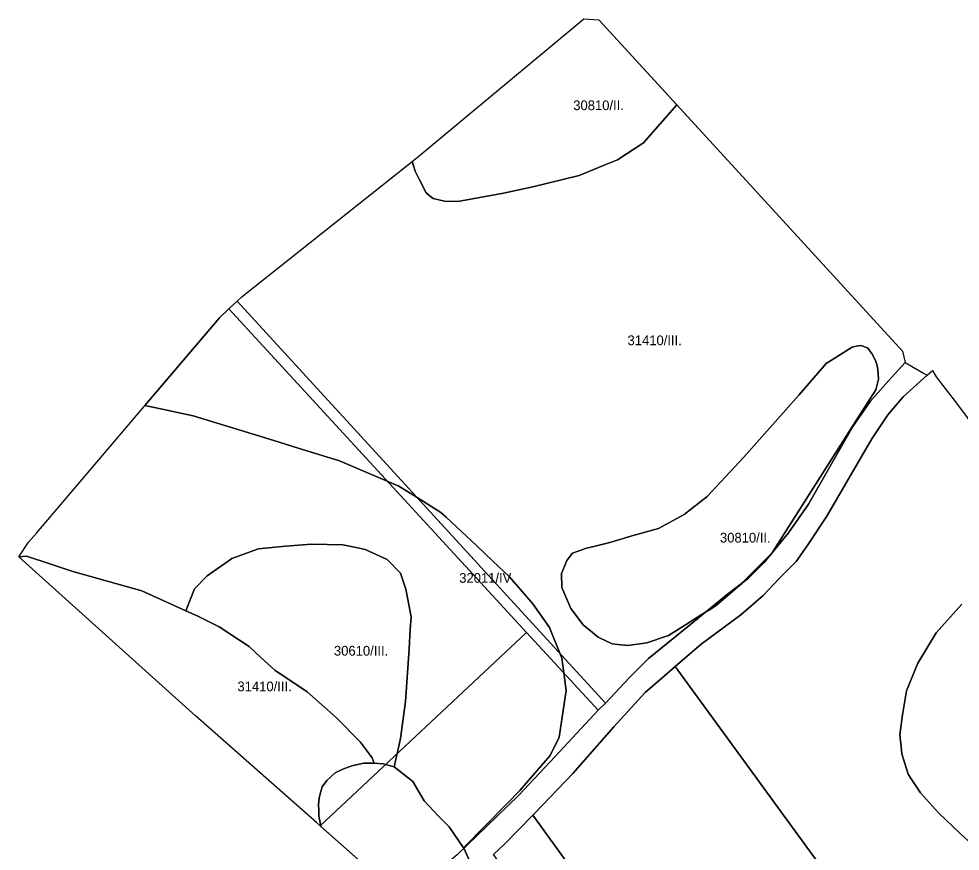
# Model space of a CAD drawing. Extents: x -522079 to -518833, y -1142400 to -1139961.
# Drawn here: x -522079.2 to -521596.1, y -1140463.4 to -1140035.9 of the extents above; entities that cross this region are included whole.
import ezdxf

# ---------------------------------------------------------------- set-up
doc = ezdxf.new("R2010")
doc.units = 0
for name, color, linetype in [('95560013', 7, 'Continuous'), ('95640013', 7, 'Continuous'), ('95660013', 7, 'Continuous')]:
    doc.layers.add(name, color=color, linetype=linetype)

msp = doc.modelspace()

# ---------------------------------------------------------------- linework, layer by layer
at = {"layer": '95560013'}
for points in [[(-521755.99, -1140364.38), (-521765.79, -1140374.26), (-521778.1, -1140387.34), (-521967.11, -1140180.95), (-521964.54, -1140178.59), (-521874.73, -1140107.13), (-521789.25, -1140035.92), (-521781.62, -1140036.36), (-521703.78, -1140121.15), (-521625.65, -1140206.61), (-521624.31, -1140212.38), (-521632.85, -1140221.77), (-521642.31, -1140232.52), (-521651.12, -1140245.38), (-521673.96, -1140285.19), (-521684.15, -1140299.89), (-521696.71, -1140315.1), (-521704.79, -1140323.18), (-521715.5, -1140331.4), (-521736.25, -1140348.4)], [(-521971.46, -1140184.95), (-521967.11, -1140180.95), (-521778.1, -1140387.34), (-521781.95, -1140390.97), (-521818.63, -1140351.09)], [(-521926.43, -1140448.75), (-521988.52, -1140393.86), (-522079.24, -1140312.2), (-522074.19, -1140304.73), (-522070.23, -1140300.06), (-521976.31, -1140189.41), (-521971.46, -1140184.95), (-521818.63, -1140351.09), (-521924.65, -1140450.32)], [(-521924.65, -1140450.32), (-521818.63, -1140351.09), (-521781.95, -1140390.97), (-521803.88, -1140414.74), (-521822.79, -1140434.86), (-521839, -1140450.48), (-521854.3, -1140465.27), (-521876.66, -1140484.09), (-521882.18, -1140488.56), (-521891.73, -1140479.43)], [(-521747.91, -1140373.33), (-521742.3, -1140368.5), (-521638.02, -1140511.86), (-521697.45, -1140535.57), (-521738.18, -1140551.68), (-521815.4, -1140444.86), (-521814.39, -1140443.83), (-521794.87, -1140423.48), (-521773.82, -1140399.6), (-521757.78, -1140381.98)], [(-521829.77, -1140459.58), (-521815.4, -1140444.86), (-521738.18, -1140551.68), (-521764.87, -1140562.24), (-521835.62, -1140465.09)]]:
    msp.add_lwpolyline(points, close=True, dxfattribs=at)
msp.add_lwpolyline([(-521592.51, -1140508.64), (-521606.9, -1140511.13), (-521606.6, -1140521.1), (-521611.18, -1140517.57), (-521625.07, -1140510.37), (-521636.41, -1140511.21), (-521638.02, -1140511.86), (-521742.3, -1140368.5), (-521728.93, -1140357.06), (-521708.67, -1140341.98), (-521697.12, -1140332.11), (-521688.85, -1140323.27), (-521680.22, -1140314.66), (-521674.58, -1140306.67), (-521664.44, -1140291.34), (-521641.46, -1140251.62), (-521633.25, -1140239.25), (-521625.36, -1140230.13), (-521613.09, -1140218.9), (-521610.22, -1140216.5), (-521608.33, -1140219.87), (-521596.95, -1140234.61), (-521579.62, -1140257.92)], dxfattribs=at)
at = {"layer": '95640013'}
msp.add_lwpolyline([(-521854.3, -1140465.27), (-521839, -1140450.48), (-521822.79, -1140434.86), (-521803.88, -1140414.74), (-521781.95, -1140390.97), (-521778.1, -1140387.34), (-521765.79, -1140374.26), (-521755.99, -1140364.38), (-521736.25, -1140348.4), (-521715.5, -1140331.4), (-521704.79, -1140323.18), (-521696.71, -1140315.1), (-521684.15, -1140299.89), (-521673.96, -1140285.19), (-521651.12, -1140245.38), (-521642.31, -1140232.52), (-521632.85, -1140221.77), (-521624.31, -1140212.38), (-521620.19, -1140214.77), (-521614.87, -1140217.86), (-521613.09, -1140218.9), (-521625.36, -1140230.13), (-521633.25, -1140239.25), (-521641.46, -1140251.62), (-521664.44, -1140291.34), (-521674.58, -1140306.67), (-521680.22, -1140314.66), (-521688.85, -1140323.27), (-521697.12, -1140332.11), (-521708.67, -1140341.98), (-521728.93, -1140357.06), (-521742.3, -1140368.5), (-521747.91, -1140373.33), (-521757.78, -1140381.98), (-521773.82, -1140399.6), (-521794.87, -1140423.48), (-521814.39, -1140443.83), (-521815.4, -1140444.86), (-521829.77, -1140459.58), (-521835.62, -1140465.09)], dxfattribs=at)
at = {"layer": '95660013'}
for points in [[(-521781.62, -1140036.36), (-521741.42, -1140080.14), (-521758.57, -1140099.56), (-521772.02, -1140108.33), (-521778.76, -1140111.12), (-521791.65, -1140116.47), (-521815.34, -1140122.25), (-521830.49, -1140125.46), (-521853.96, -1140129.74), (-521860.79, -1140129.52), (-521866.55, -1140128.24), (-521867.94, -1140127.1), (-521870.18, -1140125.25), (-521873.59, -1140118.61), (-521875.75, -1140114.18), (-521877.32, -1140109.19), (-521874.73, -1140107.13), (-521789.25, -1140035.92)], [(-522070.23, -1140300.06), (-521976.31, -1140189.41), (-522014.56, -1140234.48), (-522010.4, -1140235.32), (-521989.67, -1140239.88), (-521958.99, -1140249.25), (-521948.36, -1140252.5), (-521935.79, -1140256.37), (-521914.67, -1140262.86), (-521890.13, -1140273.36), (-521884.13, -1140275.92), (-521874.73, -1140281.82), (-521862.58, -1140289.44), (-521859.94, -1140291.89), (-521844.16, -1140306.56), (-521835.9, -1140314.4), (-521827.55, -1140322.33), (-521821.85, -1140328.89), (-521815.42, -1140336.29), (-521806.89, -1140348.46), (-521801.63, -1140361.65), (-521800.6, -1140364.23), (-521799.58, -1140371.8), (-521798.35, -1140380.9), (-521801.95, -1140404.77), (-521806.44, -1140414.24), (-521822.16, -1140432.26), (-521828.66, -1140438.92), (-521850.92, -1140461.73), (-521858.38, -1140450.93), (-521863.76, -1140445.35), (-521871.21, -1140437.63), (-521877.01, -1140427.67), (-521886.61, -1140420.14), (-521885.07, -1140413.27), (-521883.33, -1140405.55), (-521880.75, -1140386.5), (-521878.87, -1140359.44), (-521878.31, -1140349.52), (-521877.94, -1140342.97), (-521880.52, -1140328.85), (-521883.33, -1140320.62), (-521890.13, -1140313.57), (-521901.39, -1140308.39), (-521906.04, -1140307.43), (-521912.88, -1140306.03), (-521929.06, -1140305.8), (-521942.43, -1140306.74), (-521956.27, -1140308.15), (-521969.87, -1140313.09), (-521971.83, -1140314.47), (-521982.54, -1140322.03), (-521989.1, -1140328.62), (-521993.56, -1140339.91), (-522016.02, -1140329.67), (-522051.48, -1140319.82), (-522063.39, -1140315.84), (-522075.3, -1140311.87), (-522079.24, -1140312.2), (-522074.19, -1140304.73)], [(-521756.91, -1140356.37), (-521766.66, -1140357.81), (-521771.83, -1140357.25), (-521774.68, -1140356.94), (-521777.62, -1140355.53), (-521781.85, -1140353.5), (-521789.59, -1140347.17), (-521795.89, -1140338.83), (-521800.48, -1140327.91), (-521800.76, -1140320.72), (-521799.03, -1140316.71), (-521797.9, -1140314.1), (-521795.03, -1140310.36), (-521787.87, -1140307.78), (-521784.1, -1140306.88), (-521775.83, -1140304.91), (-521763.4, -1140301.11), (-521762.65, -1140300.88), (-521750.89, -1140297.72), (-521737.71, -1140290.53), (-521725.96, -1140281.33), (-521707.33, -1140261.2), (-521678.96, -1140229.29), (-521664.91, -1140212.9), (-521651.44, -1140204.56), (-521649.44, -1140203.99), (-521647.14, -1140203.7), (-521643.7, -1140204.85), (-521641.41, -1140207.73), (-521639.4, -1140211.75), (-521638.75, -1140214.2), (-521638.26, -1140216.07), (-521637.97, -1140220.95), (-521639.4, -1140226.41), (-521649.44, -1140242.23), (-521671.5, -1140277.01), (-521691.97, -1140309.36), (-521692.43, -1140310.08), (-521693.23, -1140310.89), (-521707.75, -1140325.45), (-521708.19, -1140325.89), (-521721.09, -1140337.1), (-521723.86, -1140338.86), (-521727.1, -1140340.91), (-521736.56, -1140346.88), (-521737.49, -1140347.46), (-521745.74, -1140352.63)], [(-521771.83, -1140357.25), (-521766.66, -1140357.81), (-521756.91, -1140356.37), (-521745.74, -1140352.63), (-521737.49, -1140347.46), (-521736.56, -1140346.88), (-521727.1, -1140340.91), (-521723.86, -1140338.86), (-521721.09, -1140337.1), (-521708.19, -1140325.89), (-521707.75, -1140325.45), (-521693.23, -1140310.89), (-521692.43, -1140310.08), (-521691.97, -1140309.36), (-521671.5, -1140277.01), (-521649.44, -1140242.23), (-521639.4, -1140226.41), (-521637.97, -1140220.95), (-521638.26, -1140216.07), (-521638.75, -1140214.2), (-521639.4, -1140211.75), (-521641.41, -1140207.73), (-521643.7, -1140204.85), (-521647.14, -1140203.7), (-521649.44, -1140203.99), (-521651.44, -1140204.56), (-521664.91, -1140212.9), (-521678.96, -1140229.29), (-521707.33, -1140261.2), (-521725.96, -1140281.33), (-521737.71, -1140290.53), (-521750.89, -1140297.72), (-521762.65, -1140300.88), (-521763.4, -1140301.11), (-521775.83, -1140304.91), (-521784.1, -1140306.88), (-521787.87, -1140307.78), (-521795.03, -1140310.36), (-521797.9, -1140314.1), (-521799.03, -1140316.71), (-521800.76, -1140320.72), (-521800.48, -1140327.91), (-521795.89, -1140338.83), (-521789.59, -1140347.17), (-521781.85, -1140353.5), (-521777.62, -1140355.53), (-521774.68, -1140356.94)], [(-521885.07, -1140413.27), (-521886.61, -1140420.14), (-521891.03, -1140418.85), (-521892.24, -1140418.49), (-521896.93, -1140418.26), (-521897.87, -1140415.43), (-521903.97, -1140407.2), (-521916.4, -1140394.73), (-521931.17, -1140381.56), (-521947.83, -1140370.5), (-521954.94, -1140363.87), (-521960.96, -1140358.26), (-521976.44, -1140348.15), (-521987.7, -1140342.5), (-521993.56, -1140339.91), (-521989.1, -1140328.62), (-521982.54, -1140322.03), (-521971.83, -1140314.47), (-521969.87, -1140313.09), (-521956.27, -1140308.15), (-521942.43, -1140306.74), (-521929.06, -1140305.8), (-521912.88, -1140306.03), (-521906.04, -1140307.43), (-521901.39, -1140308.39), (-521890.13, -1140313.57), (-521883.33, -1140320.62), (-521880.52, -1140328.85), (-521877.94, -1140342.97), (-521878.31, -1140349.52), (-521878.87, -1140359.44), (-521880.75, -1140386.5), (-521883.33, -1140405.55)], [(-522079.24, -1140312.2), (-522075.3, -1140311.87), (-522063.39, -1140315.84), (-522051.48, -1140319.82), (-522016.02, -1140329.67), (-521993.56, -1140339.91), (-521987.7, -1140342.5), (-521976.44, -1140348.15), (-521960.96, -1140358.26), (-521954.94, -1140363.87), (-521947.83, -1140370.5), (-521931.17, -1140381.56), (-521916.4, -1140394.73), (-521903.97, -1140407.2), (-521897.87, -1140415.43), (-521896.93, -1140418.26), (-521902.1, -1140418.23), (-521906.13, -1140419.06), (-521908.3, -1140419.5), (-521910.2, -1140420.25), (-521912.98, -1140421.34), (-521916.8, -1140423.09), (-521921.16, -1140427.15), (-521923.47, -1140430.34), (-521924.82, -1140434.72), (-521925.01, -1140436.18), (-521925.45, -1140439.5), (-521925.33, -1140442.55), (-521925.22, -1140445.48), (-521924.74, -1140447.9), (-521924.38, -1140449.7), (-521924.23, -1140450.69), (-521924.65, -1140450.32), (-521926.43, -1140448.75), (-521988.52, -1140393.86)]]:
    msp.add_lwpolyline(points, close=True, dxfattribs=at)
for points in [[(-521845.96, -1140472.52), (-521850.83, -1140461.92), (-521850.92, -1140461.73), (-521828.66, -1140438.92), (-521822.16, -1140432.26), (-521806.44, -1140414.24), (-521801.95, -1140404.77), (-521798.35, -1140380.9), (-521799.58, -1140371.8), (-521800.6, -1140364.23), (-521801.63, -1140361.65), (-521806.89, -1140348.46), (-521815.42, -1140336.29), (-521821.85, -1140328.89), (-521827.55, -1140322.33), (-521835.9, -1140314.4), (-521844.16, -1140306.56), (-521859.94, -1140291.89), (-521862.58, -1140289.44), (-521874.73, -1140281.82), (-521884.13, -1140275.92), (-521890.13, -1140273.36), (-521914.67, -1140262.86), (-521935.79, -1140256.37), (-521948.36, -1140252.5), (-521958.99, -1140249.25), (-521989.67, -1140239.88), (-522010.4, -1140235.32), (-522014.56, -1140234.48), (-521976.31, -1140189.41), (-521971.46, -1140184.95), (-521967.11, -1140180.95), (-521964.54, -1140178.59), (-521877.32, -1140109.19), (-521875.75, -1140114.18), (-521873.59, -1140118.61), (-521870.18, -1140125.25), (-521867.94, -1140127.1), (-521866.55, -1140128.24), (-521860.79, -1140129.52), (-521853.96, -1140129.74), (-521830.49, -1140125.46), (-521815.34, -1140122.25), (-521791.65, -1140116.47), (-521778.76, -1140111.12), (-521772.02, -1140108.33), (-521758.57, -1140099.56), (-521741.42, -1140080.14), (-521703.78, -1140121.15), (-521625.65, -1140206.61), (-521624.31, -1140212.38), (-521620.19, -1140214.77), (-521614.87, -1140217.86), (-521613.09, -1140218.9), (-521610.22, -1140216.5), (-521608.33, -1140219.87), (-521596.95, -1140234.61), (-521579.62, -1140257.92)], [(-521595.28, -1140336.6), (-521608.32, -1140351.33), (-521617.83, -1140366.87), (-521623.54, -1140381.04), (-521625.71, -1140393.32), (-521627.07, -1140403.67), (-521626.42, -1140409.59), (-521625.99, -1140413.49), (-521622.73, -1140423.85), (-521621.19, -1140426.19), (-521616.47, -1140433.39), (-521607.23, -1140443.75), (-521596.09, -1140454.38), (-521590.17, -1140459.55)], [(-521590.17, -1140459.55), (-521596.09, -1140454.38), (-521607.23, -1140443.75), (-521616.47, -1140433.39), (-521621.19, -1140426.19), (-521622.73, -1140423.85), (-521625.99, -1140413.49), (-521626.42, -1140409.59), (-521627.07, -1140403.67), (-521625.71, -1140393.32), (-521623.54, -1140381.04), (-521617.83, -1140366.87), (-521608.32, -1140351.33), (-521595.28, -1140336.6)], [(-521891.73, -1140479.43), (-521924.23, -1140450.69), (-521924.38, -1140449.7), (-521924.74, -1140447.9), (-521925.22, -1140445.48), (-521925.33, -1140442.55), (-521925.45, -1140439.5), (-521925.01, -1140436.18), (-521924.82, -1140434.72), (-521923.47, -1140430.34), (-521921.16, -1140427.15), (-521916.8, -1140423.09), (-521912.98, -1140421.34), (-521910.2, -1140420.25), (-521908.3, -1140419.5), (-521906.13, -1140419.06), (-521902.1, -1140418.23), (-521896.93, -1140418.26), (-521892.24, -1140418.49), (-521891.03, -1140418.85), (-521886.61, -1140420.14), (-521877.01, -1140427.67), (-521871.21, -1140437.63), (-521863.76, -1140445.35), (-521858.38, -1140450.93), (-521850.92, -1140461.73), (-521850.83, -1140461.92), (-521845.96, -1140472.52)]]:
    msp.add_lwpolyline(points, dxfattribs=at)

# ---------------------------------------------------------------- texts
for s, rotation, p in [('30810/II.', 360, (-521794.68, -1140082.83)), ('31410/III.', 0, (-521766.82, -1140203.55)), ('30810/II.', 0, (-521719.37, -1140304.9)), ('32011/IV.', 360, (-521853.19, -1140325.57)), ('30610/III.', 0, (-521917.51, -1140362.97)), ('31410/III.', 360, (-521967.04, -1140381.28))]:
    msp.add_text(s, height=5, rotation=rotation, dxfattribs=at).set_placement(p)

doc.saveas('drawing.dxf')
